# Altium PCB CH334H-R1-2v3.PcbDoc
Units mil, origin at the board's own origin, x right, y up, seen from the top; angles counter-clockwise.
Board outline 3110.24 x 866.14 mil, 2 copper layers (Top Layer, Bottom Layer); 20 components, 20 nets, 115 pads, 273 vias.
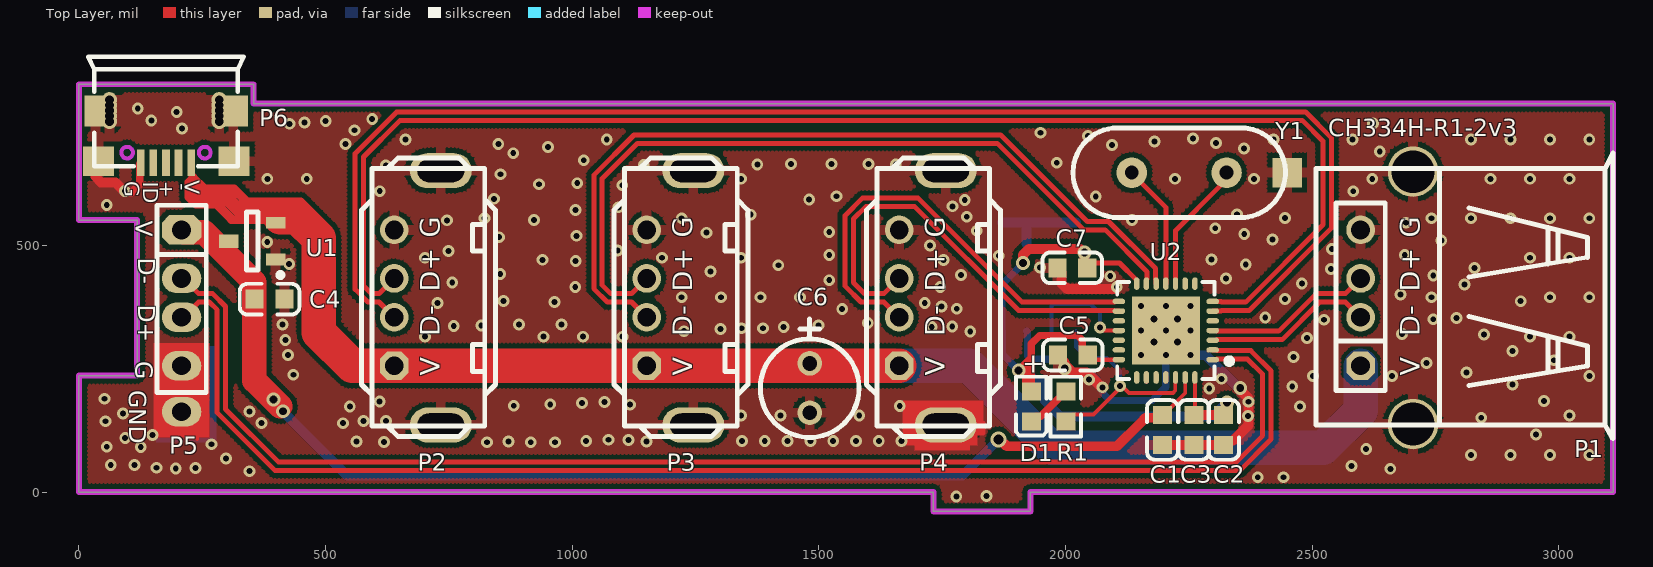
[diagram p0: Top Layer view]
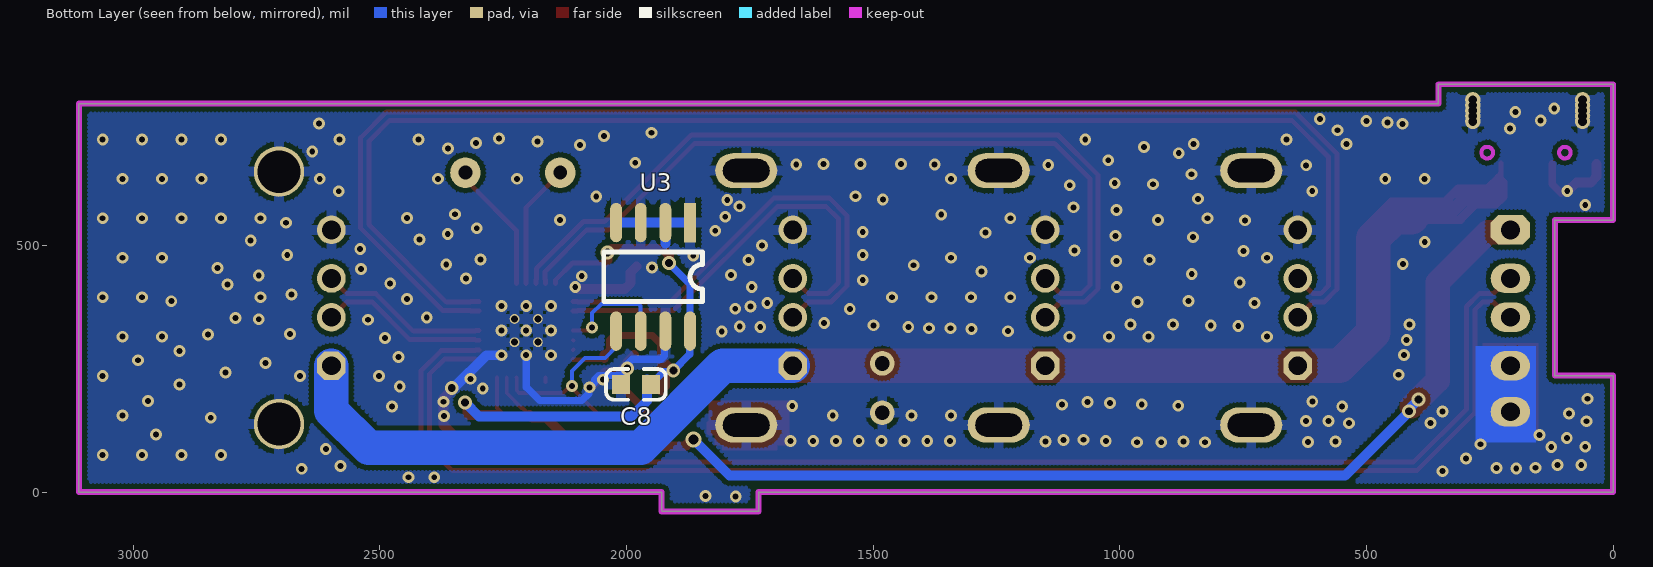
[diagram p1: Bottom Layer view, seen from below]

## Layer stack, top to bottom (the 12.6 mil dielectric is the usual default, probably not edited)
Top Solder: solder mask 0.4, Solder Resist, Dk 3.5
Top Layer: signal copper 1.4
Dielectric 1: dielectric 12.6, FR-4, Dk 4.8
Bottom Layer: signal copper 1.4
Bottom Solder: solder mask 0.4, Solder Resist, Dk 3.5

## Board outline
0,0 0,236.22 118.11,236.22 118.11,551.18 0,551.18 0,826.77 354.33,826.77 354.33,787.4 3110.24,787.4 3110.24,0 1929.13,0 1929.13,-39.37 1732.28,-39.37 1732.28,0

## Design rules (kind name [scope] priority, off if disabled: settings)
Clearance Clearance_1 [InPolygon] p1: gap=10 ignorepadtopadclearanceinfootprint=FALSE
Clearance [All] p2: gap=6 ignorepadtopadclearanceinfootprint=FALSE except(8: Arc-Via Track-Via SMDPad-Via THPad-Via Via-Via Via-Fill Via-Poly Via-Region Via-Hole)
ComponentClearance [All] p1 off: gap=10 collisioncheckmode=3 verticalgap=10 showdistances=FALSE
DiffPairsRouting [All] p1: maxlimit=10 minlimit=7 mostfreqgap=8 toplayer_minwidth=6 toplayer_maxwidth=15 toplayer_prefwidth=8 bottomlayer_minwidth=6 bottomlayer_maxwidth=15 bottomlayer_prefwidth=8 maxuncoupledlength=500
MinimumSolderMaskSliver [All] p1 off: minsoldermaskwidth=10
PolygonConnect PolygonConnect_1 [IsVia] p1: connectstyle=Direct reliefconductorwidth=10 reliefentries=4 polygonreliefangle="90 Angle" airgapwidth=10
PolygonConnect [All] p2: connectstyle=Relief reliefconductorwidth=20 reliefentries=4 polygonreliefangle="90 Angle" airgapwidth=10
RoutingVias [All] p1: holewidth=16 width=28 viastyle="Through Hole" minholewidth=12 minwidth=24 maxholewidth=28 maxwidth=50
SilkToSilkClearance [All] p1 off: silktosilkclearance=10
SilkToSolderMaskClearance [IsPad] p1 off: minsilkscreentomaskgap=10 clearancetoexposedcopper=TRUE
SolderMaskExpansion [All] p1: expansion=4 istentingtop=FALSE
Width [All] p1: maxlimit=100 minlimit=6 preferedwidth=10
25 further rules are at their usual default settings.

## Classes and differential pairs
differential pair UD: +UD_p -UD_n
differential pair UD4: +UD4_p -UD4_n
differential pair UD3: +UD3_p -UD3_n
differential pair UD2: +UD2_p -UD2_n
differential pair UD1: +UD1_p -UD1_n

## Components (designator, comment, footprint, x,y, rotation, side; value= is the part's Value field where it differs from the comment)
C1 "1uF" 0603_C 2196.7,156.36 r270 top
C2 "10uF" 0603_C 2320.79,156.36 r270 top
C3 "0.1uF" 0603_C 2260.33,156.36 r270 top
C4 "10uF" 0603_C 356.12,391.11 r0 top
C5 "1uF" 0603_C 2045.19,277.84 r180 top
C6 "220uF" CD0.1 1481.53,260.82 r270 top
C7 "1uF" 0603_C 1983.61,454.58 r0 top
C8 "NC(1uF)" 0603_C 2011.19,218.22 r180 bottom
D1 "LED" 0603+ 1930.71,203.66 r270 top
P1 "USB" USBAF#1 2598.25,255.91 r90 top
P2 "USB" USB2.0-A-F-TH_4P-V_13.7mm 639.21,255.91 r180 top
P3 "USB" USB2.0-A-F-TH_4P-V_13.7mm 1151.02,255.91 r180 top
P4 "USB" USB2.0-A-F-TH_4P-V_13.7mm 1662.83,255.91 r180 top
P5 "USB" USBAF#2 208.21,531.5 r270 top
P6 "Power Supply" USBMICROB-02-GXPX-A1T2 227.66,667.45 r180 top
R1 "1K" 0603_R 2000.69,173.35 r90 top
U1 "CH213K" SOT-23-3 398.71,471.39 r90 top
U2 "CH334H" QFN28_5X5 2203.43,327.44 r90 top
U3 "NC(24C02)" SOIC-8_150mil 1871.28,546.33 r0 bottom
Y1 "12M" XT_AT49 2326.58,647.57 r90 top

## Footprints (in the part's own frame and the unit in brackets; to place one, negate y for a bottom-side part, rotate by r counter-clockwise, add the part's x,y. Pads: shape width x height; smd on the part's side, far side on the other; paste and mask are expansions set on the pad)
0603+ [mm]
  rect 0.93x0.98 smd: 1(0,0) 2(1.54,0)
  silkscreen extent -0.76,-0.79 2.27,0.79
0603_C [mm]
  rect 0.93x0.98 smd: 1(0,0) 2(1.54,0)
  silkscreen extent -0.76,-0.79 2.31,0.79
0603_R [mm]
  rect 0.93x0.98 smd: 1(-0.77,0) 2(0.77,0)
  silkscreen extent -1.53,-0.79 1.54,0.79
CD0.1 [mil]
  round 50 hole 30: 1(0,0) 2(100,0)
  silkscreen extent -90,-100 150,100
QFN28_5X5 [mm]
  round 0.508 hole 0.356: 0(-0.6,-0.6) 0(-0.6,0.6) 0(0.6,-0.6) 0(0.6,0.6)
  rect 3.5x3.5 smd mask+0.051: 0(0,0)
  oval 0.28x0.65 smd mask+0.051: 1(-1.5,-2.416) 2(-1,-2.416) 3(-0.5,-2.416) 4(0,-2.416) 5(0.5,-2.416) 6(1,-2.416) 7(1.5,-2.416) 15(1.5,2.416) 16(1,2.416) 17(0.5,2.416) 18(0,2.416) 19(-0.5,2.416) 20(-1,2.416) 21(-1.5,2.416)
  oval 0.65x0.28 smd mask+0.051: 8(2.416,-1.5) 9(2.416,-1) 10(2.416,-0.5) 11(2.416,0) 12(2.416,0.5) 13(2.416,1) 14(2.416,1.5) 22(-2.416,1.5) 23(-2.416,1) 24(-2.416,0.5) 25(-2.416,0) 26(-2.416,-0.5) 27(-2.416,-1) 28(-2.416,-1.5)
  silkscreen extent -2.5,-3.42 2.5,2.5
SOIC-8_150mil [mil]
  rect 24x80 smd: 1(0,0)
  oval 24x80 smd: 2(50,0) 3(100,0) 4(150,0) 5(150,220) 6(100,220) 7(50,220) 8(0,220)
  silkscreen extent -25,60 175,160
SOT-23-3 [mm] "SOT-23-3"
  rect 0.6x1 smd: 1(0,0) 2(1.9,0)
  rect 0.7x1 smd: 3(0.95,2.4)
  silkscreen extent -0.93,-0.38 2.45,1.49
USB2.0-A-F-TH_4P-V_13.7mm [mm]
  oval 3.2x1.8 hole 1.2 slot 2.4 at 0 deg: 0(-2.4,3.05) 0(-2.4,-10.05)
  oct 1.473x1.473 hole 0.965: 1(0,0)
  round 1.473 hole 0.965: 2(0,-2.5) 3(0,-4.5) 4(0,-7)
  silkscreen extent -5.21,-10.71 1.69,3.65
USBAF#1 [mm]
  round 2.6 hole 2.2: 0(-3,-2.7) 0(10,-2.7)
  oct 1.473x1.473 hole 0.965: 1(0,0)
  round 1.473 hole 0.965: 2(2.5,0) 3(4.5,0) 4(7,0)
  silkscreen extent -3.75,-12.99 10.95,2.29
USBAF#2 [mm]
  oct 1.524x2.032 hole 0.965: 1(0,0)
  oval 1.524x2.032 hole 0.965: 2(2.5,0) 3(4.5,0) 4(7,0)
  silkscreen extent -1.27,-1.27 8.38,1.27
USBMICROB-02-GXPX-A1T2 [mm]
  rect 1.6x1.5 smd: 0(-2.203,-0.083) 0(4.769,-0.083)
  rect 1.5x1.6 smd: 0(-2.167,-2.675)
  round 0.8 hole 0.45: 0(-1.442,-2.134) 0(-1.442,-3.243) 0(-1.442,-2.966) 0(-1.442,-2.689) 0(-1.442,-2.411) 0(4.208,-2.689) 0(4.208,-2.411) 0(4.208,-2.134) 0(4.208,-3.243) 0(4.208,-2.966)
  rect 1.1x1.6 smd: 0(4.933,-2.675)
  rect 0.4x1.35 smd mask+0.051: 1(0,0) 2(0.65,0) 3(1.3,0) 4(1.95,0) 5(2.6,0)
  Keep-Out Layer circle w0.203: c3.3,-0.525 r0.3
  Keep-Out Layer circle w0.203: c-0.7,-0.525 r0.3
  silkscreen extent -2.7,-5.46 5.3,0.17
XT_AT49 [mil]
  rect 60x60 smd: 0(0.05,-123.12)
  round 62 hole 28: 1(0,0) 2(0,192.13)
  silkscreen extent -91,-119 91,311

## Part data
C1 C2 C3 C4 C5 C6 C7 C8: library part CAP, "Capacitor"
D1: "Typical INFRARED GaAs LED"
P1 P2 P3 P4 P5: "USB Port"
P6: library part MicroUSB, "MicroUSB Port"
R1: library part RES
U1: "Ideal Diode 5V*1A"
U2: "4 ports High-Speed USB MTT Hub with 4 over current detect"
U3: library part 24C01
Y1: library part XTAL, "Crystal Oscillator"

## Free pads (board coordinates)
  oval 80x60 hole 38: ""(208.21,162.81)

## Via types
v1: diameter 24, hole 12, Top Layer to Bottom Layer, tented both sides, 264 vias
v2: diameter 28, hole 16, Top Layer to Bottom Layer, tented both sides, 8 vias
v3: diameter 32, hole 20, Top Layer to Bottom Layer, tented both sides, 1 vias

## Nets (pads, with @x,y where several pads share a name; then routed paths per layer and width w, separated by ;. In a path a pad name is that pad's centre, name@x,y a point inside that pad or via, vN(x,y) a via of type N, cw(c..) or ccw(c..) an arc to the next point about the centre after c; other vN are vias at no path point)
3V3: C2.1 C3.1 C5.1 C7.2 C8.2 D1.1 U2.14 U2.21 U2.28 U3.8 | length 1661.3
  Top Layer w8: C3.1@2247.33,156.36 C3.1@2248.18,156.36 ; C3.1@2248.31,156.36 C3.1@2248.18,156.36 ; U2.28 2262.49,170.66 C3.1@2248.18,156.36
  Top Layer w10: C7.2@2044.91,464.4 2109.53,464.4 2143.59,430.34 2144.38,429.55 U2.14 ; C5.1@2045.19,271.84 2048.79,268.25 2108.19,268.25 U2.21
  Top Layer w15: C5.1 2034.39,288.65 2034.39,307.82 2024.74,317.46 1947.72,317.46 1930.71,300.45 1930.71,272.17 ; C2.1 2324.75,160.32 2324.75,178.86 v2(2327.24,181.35) ; v2(1905.14,246.12) 1908.65,246.12 1918.91,235.86 ; v2(1905.14,246.12) 1905.14,246.6 1930.71,272.17 ; v2(1905.14,246.12) 1907.62,248.61 1927.26,248.61 1930.71,252.06 ; 1918.91,235.86 1926.92,227.86 1930.71,227.86 ; 1918.91,235.86 1918.91,214.47 1929.72,203.66 D1.1 1930.71,227.86 ; 1930.71,227.86 1930.71,252.06 ; 1930.71,252.06 1930.71,272.17
  Top Layer w20: v2(1913.95,464.07) 1913.95,481 1925.67,492.72 2029.68,492.72 2036.71,485.69 v2(2038.87,485.69) 2038.87,470.43 C7.2@2044.91,464.4 ; C5.1@2045.19,271.84 C5.1 ; C3.1@2261.31,156.36 C2.1
  Bottom Layer w15: v2(1913.95,464.07) 1871.28,421.39 U3.8 1871.5,326.11 1871.5,279.76 v2(1905.14,246.12) 1906.88,244.38 1924.4,244.38 C8.2
  Bottom Layer w20: C8.2@1958.87,227.91 1958.87,184.36 1990.17,153.06 2298.95,153.06 v2@2326.84,180.95 ; v2(2038.87,485.69) v2@2038.87,487.86
5V: C1.1 C4.1 P5.1 U1.3 U2.27 | length 2504
  Top Layer w8: C1.1 2211,170.66 2212.67,170.66 2242.8,200.8 U2.27
  Top Layer w20: v2(413.57,163.84) 416.2,163.84 v2@422.95,170.59 ; v3(1864.36,106.36) 1867.61,106.36 1881.04,92.93 2104.87,92.93 2150.77,138.83 2162.48,150.54 2190.89,150.54 C1.1
  Top Layer w50: P5.1 212.86,526.85 254.01,526.85 355.63,425.23 355.63,226.31 380.94,201 v2@407.93,174.01
  Bottom Layer w20: v2(394.44,187.5) 413.57,168.37 v2(413.57,163.84) 413.57,162.77 543,33.35 1791.35,33.35 v3(1864.36,106.36)
GND: C1.2 C2.2 C3.2 C4.2 C5.2 C6.2 C7.1 C8.1 P1.0 P1.4 P2.0 P2.4 P3.0 P3.4 P4.0 P4.4 P5.4 P6.0 P6.5 pad. U1.1 U2.0 U3.1 U3.2 U3.3 U3.4 U3.7 Y1.0 | length 2165.3
  Top Layer w8: 222,112.53 222,206.65 ; 225,112.53 225,206.65 ; 230,111.08 230,205.21 ; 233,204.17 233,298.3 ; 234,111.08 234,205.21 ; 240,107.99 240,295.21 ; 1834.11,119.74 1834.11,140.29
  Top Layer w15: 104.84,605.5 123.71,624.36 P6.5@123.71,665.85
  Top Layer w20: P6.0@33.46,665 33.46,639.41 45.12,627.76 74.35,627.76 91.94,610.17 v1(93.02,610.17) ; C7.1@1980.04,457.09 1980.11,457.09 1991.92,445.28 1991.92,423.18 2003.63,411.47 2098.94,411.47 2102.91,415.43 v1(2103.99,415.43) ; C5.2 1984.56,276.86 1998.66,262.77 1998.66,256.58 2000.82,256.58 2014.85,242.55 2043.13,242.55 v1@2074.3,211.38 ; C1.2 C3.2@2247.33,95.73 ; C3.2 C2.2 2329.09,104.03 2339.7,104.03 2371.08,135.41 2371.08,190.22 2354.33,206.97 v2(2354.33,210.95)
  Bottom Layer w15: U3.7 1923,324.61 1923,276.07 1930.06,269.01 1988.97,269.01 2000.38,257.59 2000.38,247.03 2011.19,236.22 2056.13,236.22 2064.92,227.43 2064.92,221.46 v1@2074.65,211.73 ; v1(2075.26,212.34) 2076.99,210.62 2076.99,199.15 2090.6,185.53 2176.09,185.53 2203.43,212.88 v1(2203.43,277.44)
  Bottom Layer w20: U3.1 U3.2 ; 1921.32,503.34 U3.2 U3.2 ; U3.4 U3.3 U3.2 ; v1(2253.43,277.44) 2284.28,277.44 2349.24,212.48 2352.8,212.48 v2(2354.33,210.95)
  other v1: 1778.73,-8.71 1840.22,-8.03 2389.86,29.95 2441.72,29.95 345.77,42.29 2658.59,47.16 196.36,47.86 157.58,49.29 236.59,48.81 2580.06,52.54 64.67,55.04 112.56,54.56 298,68.06 2822,75 2902,75 2982,75 3062,75 2609.65,86.96 125.49,91.43 56.53,91.91 269.09,96.97 618.87,101.5 827.57,100.97 916.07,100.97 965.42,100.97 563.05,102.8 870.97,102.68 1150.93,102.68 1344.12,103.19 1390.38,103.19 1436.63,103.19 1482.89,103.19 1529.14,103.19 1575.4,103.19 1621.65,103.19 1667.91,103.19 1028.39,103.53 1114.34,105.23 1073.49,106.08 93.89,109.63 149.43,115.38 2953.66,116.98 370.18,139.83 535.35,139.58 54.14,143.63 576.89,143.91 622.77,143.91 2842.89,150.73 2370.11,153.94 1342,155 1422,155 1582,155 3022,155 89.58,159.43 345.61,163.53 549.2,173.34 2475.8,173.13 1664.05,174.13 881.63,174.96 1117.55,177.16 955.63,177.89 1020.11,180.82 1065.53,182.28 2370.74,183.04 609.78,183.72 2970.04,184.47 51.74,189.12 2291.46,209.68 2459.83,213.82 2906.47,218.22 2048.03,227.78 2316.63,229.6 2502,235 2662,235 3062,235 434.69,237.84 2813.04,242.58 2732.05,261.79 2990.27,267.24 2462.41,273.56 2153.43,277.44 423.87,277.65 2906.47,285.71 418.52,308.01 2489.59,312.02 702,315 942,315 1022,315 1102,315 2942,315 3022,315 2848.67,319.45 2681.97,320.55 1226.76,326.1 1807.05,325.77 2153.43,327.44 2203.43,327.44 2253.43,327.44 1300.83,330.59 1343.48,332.09 1386.87,332.09 1428.77,334.33 1729.02,334.29 1770.46,335.58 760.01,336.88 815.69,337.61 1499.1,338.07 412.77,339.4 891.89,339.81 978.34,339.81 1599.31,342.91 2524.42,349.34 2745.54,350.41 2792.74,353.2 2404.99,354.16 1547.41,370.82 1779.67,371.61 1749.02,376.08 2153.43,377.44 2203.43,377.44 2253.43,377.44 727.04,383.04 1714.7,382.93 964.42,385.23 861.12,387.43 2922.84,386.94 2445.1,391.24 1222,395 1302,395 1382,395 1462,395 2742,395 2982,395 3062,395 2679.08,400.49 1006.25,415.39 1746.14,415.53 2809.11,420.69 2479.16,423.03 756.97,424.97 1521.18,429.51 2325.64,432.94 2090.74,437.63 2745.54,439.02 1788.13,440.28 854.15,442.07 1280.14,447.3 2538.36,452.08 2829.34,454.43 1948.64,455.3 1417.86,459.82 2365.53,461.29 426.3,462.16 1007.16,468.13 1752.63,470.43 939.67,470.84 2296.25,471.78 702,475 1182,475 1342,475 2942,475 3022,475 1864.76,479.09 2687.75,480.44 1521.18,480.68 749.2,488.72 1092.03,489.51 2540,492.69 1725.48,499.88 381.83,506.92 2761.91,510.3 2419.59,511.67 851.82,516.71 1009,519.49 2362.38,523.22 1272.17,525.84 1521.18,527.32 1820.16,529.73 2303.59,534.77 2690.64,545.94 746.09,550.91 2134.92,551.32 922.56,551.69 822,555 1222,555 2742,555 2822,555 2902,555 2982,555 3062,555 2444.78,555.76 1799.93,558.04 1362.09,562.26 2347.68,563.11 1006.71,571.47 1093.71,577.24 1770.67,579.29 56.52,582.14 1795.89,592.13 1480.46,592.99 841.71,594.45 2061.44,599.41 1535.62,599.64 609.99,609.92 2583.48,609.77 1101.53,621.94 932.67,623.99 1010.25,626.12 382,635 462,635 1342,635 2222,635 2382,635 2622,635 2862,635 2942,635 3022,635 854.93,644.21 622.24,662.42 1145.12,662.73 1375.3,663.89 1655.97,663.89 1443.81,664.72 1525.54,664.72 1600.66,664.72 1982.36,667.55 1023.41,672.66 880.58,686.96 2637.09,690.68 2362.28,696.61 951.33,699.4 2094.66,703.29 540.34,705.78 850.26,705.62 2305.11,707.71 2180.82,710.71 662,715 1070.19,714.85 2422,715 2582,715 2822,715 2902,715 2982,715 3062,715 2258.52,716.97 2045.64,721.53 1949.23,728.4 559.03,733.42 209.17,737.14 426.68,746.52 2623.79,747.43 457.39,749.48 500.31,752.44 146.87,753.14 594.56,756.21 198.29,770.28 119.32,777.75
  other v2: 1998.66,250.58
NetD1_2: D1.2 R1.2 | length 95.1
  Top Layer w15: D1.2 1941.51,153.84 1949.88,153.84 1999.71,203.66 R1.2
NetU2_10: U2.10 Y1.1 | length 273.7
  Top Layer w10: U2.10 2223.12,530.04 2311.08,618 Y1.1@2340.65,647.57
NetU2_11: U2.11 Y1.2 | length 253.6
  Top Layer w10: Y1.2 2134.45,646.27 2203.43,577.28 U2.11
RST: U2.17
SCL: U2.18 U3.6 | length 230.5
  Top Layer w8: v1@2065.68,327.44 U2.18
  Bottom Layer w8: U3.6 1971.28,376.84 1975.96,381.52 2051.05,381.52 2070,362.57 v1(2070,333.79)
SDA: R1.1 U2.26 U3.5 | length 460.7
  Top Layer w8: R1.1 2015,157.34 2057.1,157.34 2110.35,210.59 v1(2110.35,214.92) 2114.68,214.92 2128.42,201.18 2217.85,201.18 2222.54,205.87 2222.54,231.76 U2.26
  Bottom Layer w8: U3.5 2021.28,314.41 2021.28,294 2043.14,272.14 2083.9,272.14 2110.35,245.68 v1(2110.35,214.92)
UD1_n: P1.2 U2.3 | length 344.6
  Top Layer w10: U2.3 2306.1,307.76 2307.44,309.1 2439.25,309.1 2515.35,385.2 2567.38,385.2 P1.2
UD1_p: P1.3 U2.4 | length 344.6
  Top Layer w10: U2.4 2306.1,327.44 2307.44,326.1 2432.21,326.1 2508.31,402.2 2567.38,402.2 P1.3
UD2_n: P2.2 U2.6 | length 2907
  Top Layer w10: P2.2 608.34,385.2 585.78,385.2 559.96,411.02 559.96,686.25 644.11,770.4 2486.98,770.4 2539.02,718.36 2539.02,534.91 2372.27,368.15 2316.49,368.15 2315.34,367.01 2298.73,367.01 U2.6
UD2_p: P2.3 U2.7 | length 2794.3
  Top Layer w10: P2.3 608.34,402.2 592.82,402.2 576.96,418.07 576.96,679.21 651.15,753.4 2479.94,753.4 2522.02,711.32 2522.02,541.95 2365.23,385.15 2316.49,385.15 2315.34,386.3 2298.73,386.3 U2.7
UD3_n: P3.2 U2.12 | length 1677.1
  Top Layer w10: P3.2 1120.15,385.2 1071.13,385.2 1043.9,412.43 1043.9,642.56 1125.3,723.96 1868.8,723.96 2044.14,548.62 2087.38,548.62 2182.41,453.59 2182.41,431.45 2183.75,430.11 U2.12
UD3_p: P3.3 U2.13 | length 1592.6
  Top Layer w10: P3.3 1120.15,402.2 1078.17,402.2 1060.9,419.47 1060.9,635.52 1132.34,706.96 1861.76,706.96 2037.1,531.62 2080.33,531.62 2165.41,446.55 2165.41,431.45 2164.06,430.11 U2.13
UD4_n: P4.2 U2.15 | length 936.4
  Top Layer w10: P4.2 1631.96,385.2 1585.55,385.2 1553.24,417.51 1553.24,560.76 1588.23,595.75 1701.47,595.75 1912.06,385.15 2099.43,385.15 2100.77,386.5 U2.15
UD4_p: P4.3 U2.16 | length 880.1
  Top Layer w10: P4.3 1631.96,402.2 1592.59,402.2 1570.24,424.55 1570.24,553.72 1595.27,578.75 1694.43,578.75 1905.02,368.15 2099.43,368.15 2100.77,366.81 U2.16
UD_n: P5.2 U2.1 | length 2729.1
  Top Layer w10: P5.2 211.83,433.07 242.7,402.2 271.31,402.2 297.25,376.26 297.25,168.13 404.84,60.54 2345.95,60.54 2399.69,114.28 2399.69,238.93 2368.89,269.73 2307.44,269.73 2306.1,268.39 U2.1
UD_p: P5.3 U2.2 | length 2785.4
  Top Layer w10: P5.3 211.83,354.33 242.7,385.2 264.27,385.2 280.25,369.22 280.25,161.09 397.8,43.54 2352.99,43.54 2416.69,107.24 2416.69,245.97 2375.93,286.73 2307.44,286.73 2306.1,288.07 U2.2
VBUS: C6.1 P1.1 P2.1 P3.1 P4.1 P6.1 U1.2 | length 4541.8
  Top Layer w10: 247.13,591.38 252.13,591.38 ; 252.85,603.63 251.45,605.02 ; 252.85,608.63 252.85,605.02 ; 254.37,584.14 259.37,584.14 ; 264.41,611.02 311.02,611.02 ; 267.21,605.02 262.21,605.02 ; 276.12,579.63 263.88,579.63 ; 300.6,595.14 304.36,591.38 ; 310.6,584.14 298.62,584.14 ; 316.1,591.38 304.36,591.38 ; U1.2@406.86,555.78 326.98,555.78 ; 414.92,583.36 412.13,586.15 348.56,586.15 ; 472.04,570.76 450.45,592.36 342.35,592.36 ; 219.15,602.21 241.73,579.63 ; 219.15,602.21 219.15,629.22 226.76,636.83 226.76,666.54 P6.1 P6.1@227.66,646.78 ; 219.15,602.21 219.15,597.21 236.73,579.63 241.73,579.63 ; 227.66,615.85 227.66,619.83 ; 227.66,615.85 227.66,604.47 252.5,579.63 ; 227.66,615.85 238.49,605.02 ; 227.66,619.83 227.66,628.81 ; 227.66,619.83 242.47,605.02 ; 227.66,628.81 251.45,605.02 ; 227.66,628.81 P6.1@227.66,646.78 ; P6.1@227.66,646.78 234.14,640.3 ; 234.14,640.3 255.62,618.81 ; 234.14,640.3 234.14,633.09 248.42,618.81 ; 238.49,605.02 242.47,605.02 ; 238.49,605.02 252.13,591.38 ; 241.73,579.63 252.5,579.63 ; 242.47,605.02 251.45,605.02 ; 242.47,605.02 247.47,600.02 257.85,600.02 ; 248.42,618.81 262.21,605.02 ; 248.42,618.81 255.62,618.81 ; 251.45,605.02 252.85,605.02 ; 252.13,591.38 266.49,591.38 ; 252.13,591.38 259.37,584.14 ; 252.5,579.63 263.88,579.63 ; 252.85,605.02 262.21,605.02 ; 252.85,605.02 257.85,600.02 ; 255.62,618.81 272.06,602.38 ; 255.62,618.81 303.23,618.81 ; 257.85,600.02 266.49,591.38 ; 257.85,600.02 267.21,600.02 ; 259.37,584.14 272.6,584.14 ; 259.37,584.14 263.88,579.63 ; 262.21,605.02 264.85,602.38 ; 264.85,602.38 272.06,602.38 ; 264.85,602.38 267.21,600.02 ; 266.49,591.38 304.36,591.38 ; 267.21,600.02 274.41,600.02 ; 272.06,602.38 306.1,602.38 ; 272.06,602.38 274.41,600.02 ; 272.6,584.14 300.96,555.78 ; 272.6,584.14 266.12,590.63 278.35,590.63 ; 272.6,584.14 284.83,584.14 ; 274.41,600.02 303.75,600.02 306.1,602.38 ; 278.35,590.63 284.83,584.14 ; 278.35,590.63 292.14,590.63 298.62,584.14 ; 284.83,584.14 313.2,555.78 ; 284.83,584.14 298.62,584.14 ; 298.62,584.14 326.98,555.78 ; 300.96,555.78 308.44,548.3 406.24,548.3 408.21,550.26 408.21,557.56 408.21,564.86 ; 300.96,555.78 313.2,555.78 ; 303.23,618.81 315.9,618.81 342.35,592.36 ; 303.23,618.81 311.02,611.02 ; 304.36,591.38 330.88,564.86 408.21,564.86 ; 306.1,602.38 335.62,572.86 400.21,572.86 ; 311.02,611.02 335.9,586.15 ; 313.2,555.78 326.98,555.78 ; 335.9,586.15 339.66,582.39 352.32,582.39 ; 335.9,586.15 348.56,586.15 ; 342.35,592.36 348.56,586.15 ; 348.56,586.15 352.32,582.39 ; 352.32,582.39 390.69,582.39 400.21,572.86 ; 400.21,572.86 408.21,564.86
  Top Layer w70: U1.2@408.21,557.56 443.11,557.56 486.59,514.09 486.59,323.48 554.17,255.91 P2.1 P3.1 P4.1
  Bottom Layer w70: P4.1 1805.45,255.91 1971.47,89.88 2523.05,89.88 2598.25,165.09 P1.1
pads on no net: P6.2 P6.3 P6.4 U2.5 U2.8 U2.9 U2.19 U2.20 U2.22 U2.23 U2.24 U2.25
copper on no net: | length 18.2
  Top Layer w8: 2107.75,288.65 2108.33,288.07 ; 2107.75,307.18 2108.33,307.76 ; 2164.06,222.8 2164.06,232.34
  Top Layer w10: 2203.43,225.33 2203.43,232.34

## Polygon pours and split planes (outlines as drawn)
GND on Top Layer "GND" (hatched 90Degree grid 8 track 8, remove dead copper, pour order 0): 0,826.77 0,551.18 118.11,551.18 118.11,236.22 0,236.22 0,0 1732.28,0 1732.28,-39.37 1929.13,-39.37 1929.13,0 3110.24,0 3110.24,787.4 354.33,787.4 354.33,826.77
GND on Bottom Layer "GND" (hatched 90Degree grid 8 track 8, remove dead copper, pour order 1): 0,826.77 0,551.18 118.11,551.18 118.11,236.22 0,236.22 0,0 1732.28,0 1732.28,-39.37 1929.13,-39.37 1929.13,0 3110.24,0 3110.24,787.4 354.33,787.4 354.33,826.77

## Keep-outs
Keep-Out Layer:
  the board outline again, w12

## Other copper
Top Layer:
  rectangle net GND: 1694,84.44 1806,101.7
  rectangle net GND: 1668.7,94.34 1822.2,119.41
  rectangle net GND: 1669.7,115 1834.11,185.26
  rectangle net GND: 151.31,111.08 265.24,302.38
Bottom Layer:
  rectangle net GND: 156.56,100.86 278.7,295.9

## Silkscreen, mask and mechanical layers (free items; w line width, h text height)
Top Overlay:
  text "CH334H-R1-2v3" at 2532.39,721.18 h35
  text "GND" at 102.23,206.83 h35 r270
Mechanical 1:
  lines w10: 0,0 0,236.22 118.11,236.22 118.11,551.18 0,551.18 0,787.4 0,826.77 354.33,826.77 354.33,787.4 3110.24,787.4 3110.24,0 1929.13,0 1929.13,-39.37 1732.28,-39.37 1732.28,0 0,0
